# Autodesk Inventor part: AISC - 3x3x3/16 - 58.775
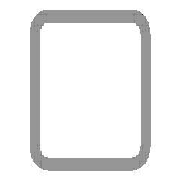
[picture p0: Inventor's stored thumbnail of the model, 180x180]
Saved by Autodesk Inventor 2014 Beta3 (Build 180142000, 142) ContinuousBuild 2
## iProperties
_CCFamilyMember: 9
_CCFamilyDisplayName: ANSI AISC (Square) - Tube
_FrameMemberDoc: Frame Member File
_Version: 15.0.0
_GetPNFromCC: 1
Created: 2011-01
Part Number: AISC - 3x3x3/16 - 58.775
Material: Steel, Mild
Description: Tube
Document SubType Name: Modeling
Standard: ANSI
Designer: Beta-8540w
Standards Organization: ANSI
Language: en-US
Size Designation: 3x3x3/16
Categories: <MemberInstance><Categories><Category DisplayName="Structural Shapes" InternalName="089c4875-fa83-4c05-b084-43b9cc11f5ed" Mnemonic="GRDR"><CategoryParameter Dis
Stock Number: 3x3x3/16
Density: 7.86 g/cm^3
Appearance: Steel
IsCustomPart: 1
G_L: 58.775 in
G_W: 3.000 in
G_H: 3.000 in
+C0B2F2CA-6D80-4947-9DF6-0D09030B4A40+CUTDETAIL1: Cut
Author: Beta-8540w
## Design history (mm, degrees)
node "Start plane"
node "End plane"
sketch "Sketch"
  geometry: L1 (-38.1, -28.575)-(-38.1, 28.575); L2 (-28.575, 38.1)-(28.575, 38.1); L3 (38.1, 28.575)-(38.1, -28.575); L4 (28.575, -38.1)-(-28.575, -38.1); L5 (-28.575, 33.337)-(28.575, 33.338); L6 (33.338, 28.575)-(33.338, -28.575); L7 (28.575, -33.337)-(-28.575, -33.338); L8 (-33.338, -28.575)-(-33.338, 28.575); L9 (0, 56.102)-(0, -56.102) reference; L10 (-56.102, 0)-(56.102, 0) reference; A1 r 9.525 centre (-28.575, -28.575) between (-38.1, -28.575) and (-28.575, -38.1); A2 r 9.525 centre (-28.575, 28.575) between (-28.575, 38.1) and (-38.1, 28.575); A3 r 9.525 centre (28.575, 28.575) between (38.1, 28.575) and (28.575, 38.1); A4 r 9.525 centre (28.575, -28.575) between (28.575, -38.1) and (38.1, -28.575); A5 r 4.763 centre (-28.575, 28.575) between (-28.575, 33.337) and (-33.338, 28.575); A6 r 4.763 centre (28.575, 28.575) between (33.338, 28.575) and (28.575, 33.338); A7 r 4.763 centre (28.575, -28.575) between (28.575, -33.337) and (33.338, -28.575); A8 r 4.763 centre (-28.575, -28.575) between (-33.338, -28.575) and (-28.575, -33.338)
  constraints: 16 end point, 16 point on circle, 8 centre point, 8 tangent, 4 parallel, 3 equal radius, 2 perpendicular, 7 other
  dimensions: "d10" = 76.2 distance between parallel lines of L2 L4 (= G_H); "d11" = 76.2 distance between parallel lines of L1 L3 (= G_W); "d12" = 4.7625 distance between parallel lines of L3 L6 (= G_T); "d15" = 38.1 distance between parallel lines of L2 L10 (= 0.5 x d10); "d16" = 38.1 distance between parallel lines of L9 L3 (= 0.5 x d11); "d17" = 9.525 radius of A1 (= G_IR)
extrude "Body" new body sketch "Sketch" stored distance "d3" = 1492.89148 (= G_L); taper "d4" = 0 deg
node "Driven Length"
  sketch "Sketch3"
    geometry: L1 (0, 0)-(10, 0) reference
    constraints: 2 end point, 1 horizontal
  workplane "Work Plane3"
  sketch "Sketch4"
    geometry: L1 (-2, 31.109)-(12, 31.109) reference; L2 (-2, 1524)-(12, 1524) reference
    dimensions: "d19" = 1492.89148 distance between parallel lines of L1 L2 (derived)
workplane "Work Plane4"
split "Split1"
body "Solid1"
other parameters: "G_W" = 76.2 [user parameter; used in 1 equation term], "G_H" = 76.2 [user parameter; used in 1 equation term], "G_T" = 4.7625 [user parameter; used in 1 equation term], "G_IR" = 9.525 [user parameter; used in 1 equation term], "G_L" = 1492.89148 (= d19) [user parameter; used in 1 equation term], "G_OFFSET_START" = -31.10852 [user parameter; used in 1 equation term], "G_OFFSET_END" = 0 [user parameter; used in 1 equation term], "d13" = 31.10852 (= -G_OFFSET_START), "d14" = 1524 (= G_OFFSET_END + B_L), "B_L" = 1524 [user parameter; used in 1 equation term], "d18" = 90 deg
